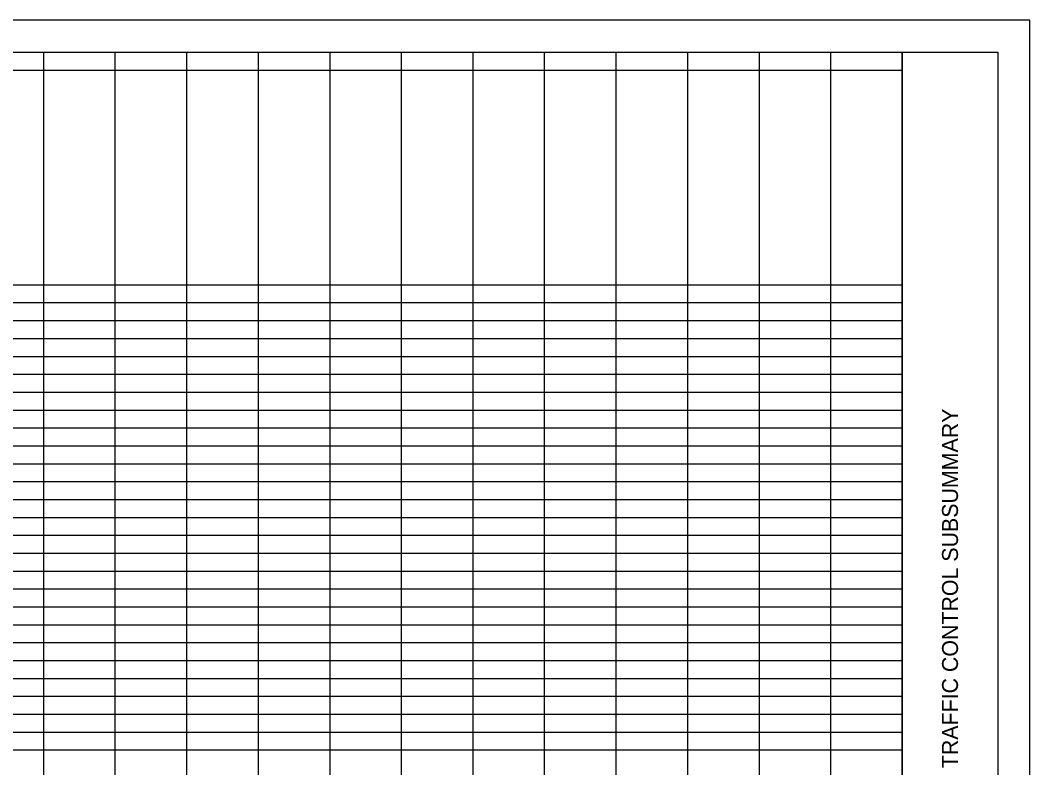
# Model space of a CAD drawing. Extents: x -0.1 to 36.3, y 0 to 22.
# Drawn here: x 18.07 to 33.88, y 10.28 to 21.98 of the extents above; entities that cross this region are included whole.
import ezdxf

# ---------------------------------------------------------------- set-up
doc = ezdxf.new("R2010")
doc.units = 0
for name, color, linetype in [('Default', 7, 'Continuous'), ('SH_Border', 7, 'Continuous'), ('SH_Cut_Line', 7, 'Continuous'), ('SH_Data', 7, 'Continuous')]:
    doc.layers.add(name, color=color, linetype=linetype)

msp = doc.modelspace()

# ---------------------------------------------------------------- linework, layer by layer
at = {"layer": 'Default'}
for p, q in [((1.376, 21.475), (31.876, 21.475)), ((18.43, 21.475), (18.43, 0.475)), ((19.55, 21.475), (19.55, 0.475)), ((20.671, 21.475), (20.671, 0.475)), ((21.791, 21.475), (21.791, 0.475)), ((22.912, 21.475), (22.912, 0.475)), ((24.032, 21.475), (24.032, 0.475)), ((25.153, 21.475), (25.153, 0.475)), ((26.273, 21.475), (26.273, 0.475)), ((27.394, 21.475), (27.394, 0.475)), ((28.514, 21.475), (28.514, 0.475)), ((29.635, 21.475), (29.635, 0.475)), ((30.755, 21.475), (30.755, 0.475)), ((31.876, 21.475), (31.876, 0.475)), ((9.466, 21.195), (31.876, 21.195)), ((8.362, 17.835), (31.876, 17.835)), ((1.376, 17.555), (31.876, 17.555)), ((1.376, 17.275), (31.876, 17.275)), ((1.376, 16.995), (31.876, 16.995)), ((1.376, 16.715), (31.876, 16.715)), ((1.376, 16.435), (31.876, 16.435)), ((1.376, 16.155), (31.876, 16.155)), ((1.376, 15.875), (31.876, 15.875)), ((1.376, 15.595), (31.876, 15.595)), ((1.376, 15.315), (31.876, 15.315)), ((1.376, 15.035), (31.876, 15.035)), ((1.376, 14.755), (31.876, 14.755)), ((1.376, 14.475), (31.876, 14.475)), ((1.376, 14.195), (31.876, 14.195)), ((1.376, 13.915), (31.876, 13.915)), ((1.376, 13.635), (31.876, 13.635)), ((1.376, 13.355), (31.876, 13.355)), ((1.376, 13.075), (31.876, 13.075)), ((1.376, 12.795), (31.876, 12.795)), ((1.376, 12.515), (31.876, 12.515)), ((1.376, 12.235), (31.876, 12.235)), ((1.376, 11.955), (31.876, 11.955)), ((1.376, 11.675), (31.876, 11.675)), ((1.376, 11.395), (31.876, 11.395)), ((1.376, 11.115), (31.876, 11.115)), ((1.376, 10.835), (31.876, 10.835)), ((1.376, 10.555), (31.876, 10.555))]:
    msp.add_line(p, q, dxfattribs=at)
at = {"layer": 'SH_Border'}
msp.add_line((31.876, 0.475), (31.876, 21.475), dxfattribs=at)
msp.add_lwpolyline([(1.376, 21.475), (33.376, 21.475), (33.376, 0.475), (1.376, 0.475)], close=True, dxfattribs=at)
at = {"layer": 'SH_Cut_Line'}
msp.add_lwpolyline([(-0.124, -0.025), (33.876, -0.025), (33.876, 21.975), (-0.124, 21.975)], close=True, dxfattribs=at)

# ---------------------------------------------------------------- texts
at = {"layer": 'SH_Data'}
msp.add_text('TRAFFIC CONTROL SUBSUMMARY', height=0.25, rotation=90, dxfattribs=at).set_placement((32.751, 10.27))

doc.saveas('drawing.dxf')
